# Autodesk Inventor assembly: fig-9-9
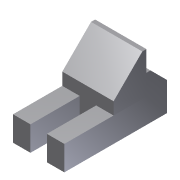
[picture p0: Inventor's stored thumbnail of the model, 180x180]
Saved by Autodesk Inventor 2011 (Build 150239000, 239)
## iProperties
Shininess: 64.0
Length Units: 11269
Angle Units: 11279
Time Units: 11290
Mass Units: 11283
Length Display Precision: 3
Angle Display Precision: 2
Created: 2002-01
Part Number: fig-9-9
Document SubType Name: Assembly
Designer: ***
Density: 0.0
Volumn: 0.0
Area: 0.0
PropertySet Name: Model Information
Control State: 0
Master: False
Checked Out: False
Author: ***
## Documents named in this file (3)
- C:\Users\CADSoft\Desktop\part files\c09-inv-2011-prt\fig-9-9.iam
- C:\Users\CADSoft\Desktop\inventor\c09-inv-2010-prt\c09\Part3.ipt
- C:\Users\CADSoft\Desktop\inventor\c09-inv-2010-prt\c09\Part4.ipt
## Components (2 placed, 2 different names)
1. Part3:1 — Mate:1
2. Part4:1 — Mate:1
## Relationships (1: Mate 1)
- Mate:1: Part3:1 ↔ Part4:1
